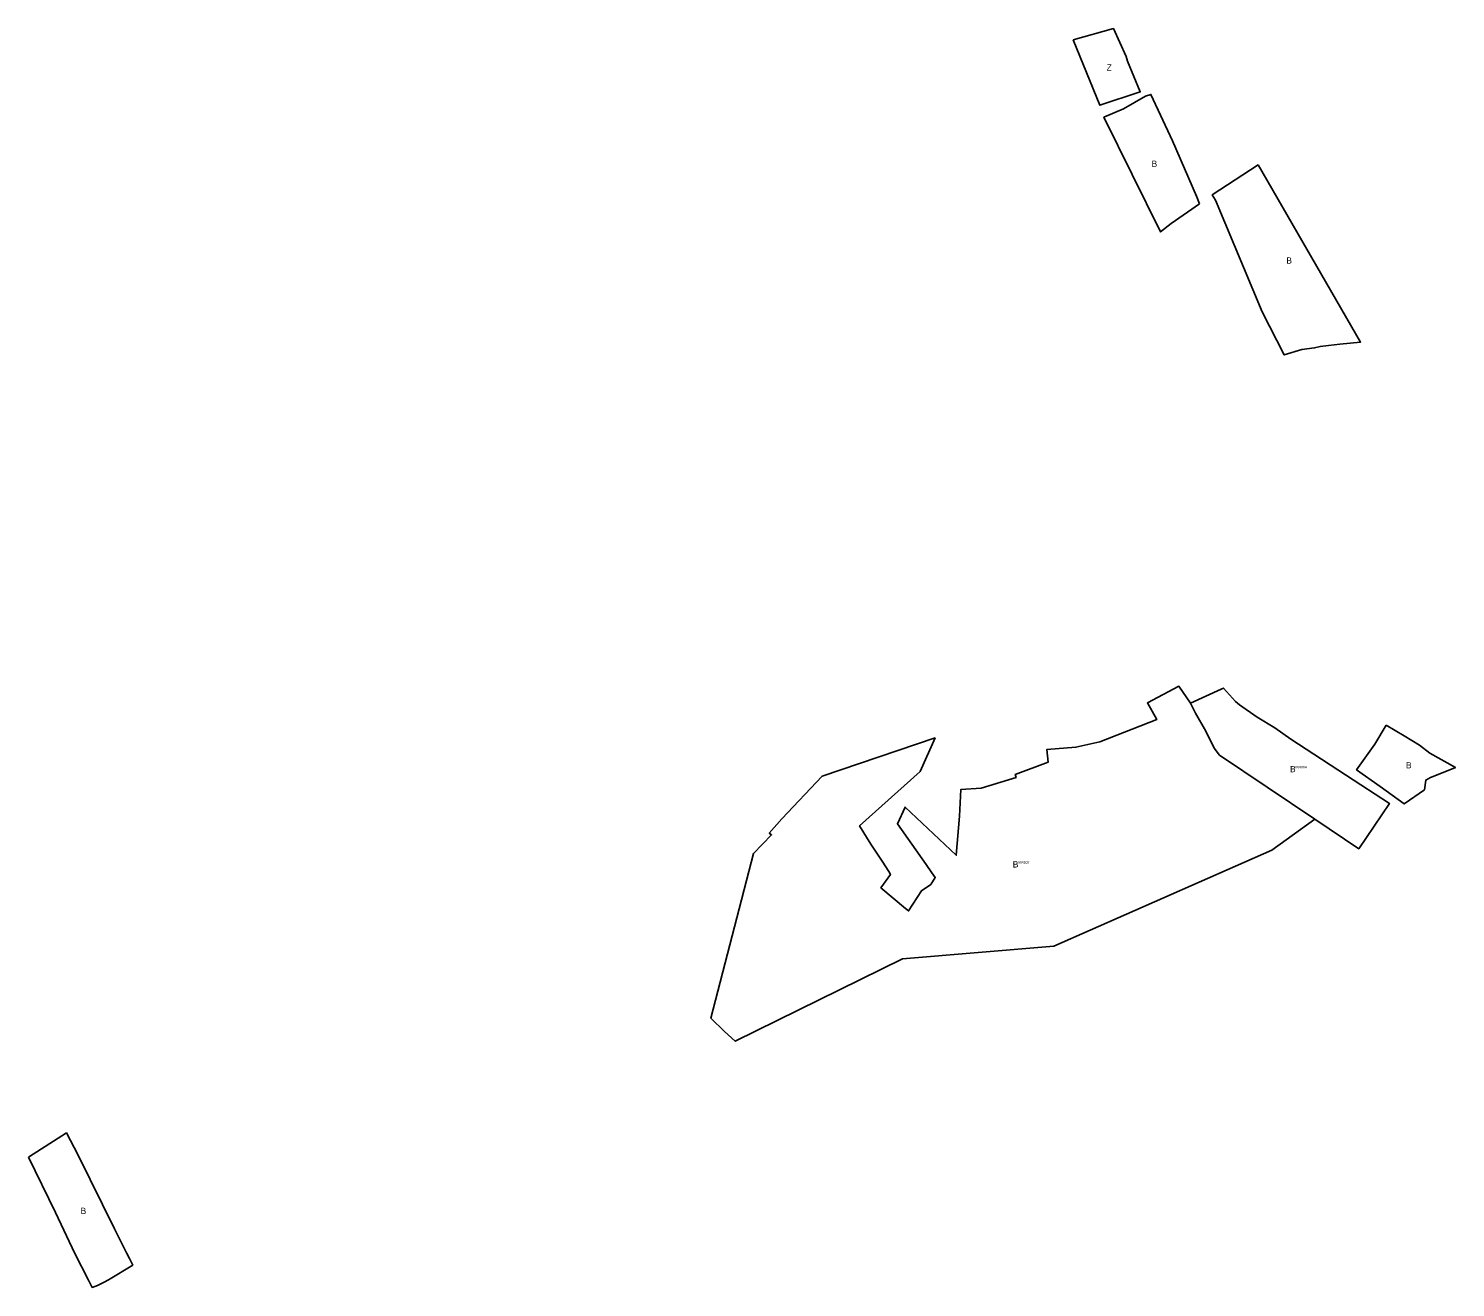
# Model space of a CAD drawing. Extents: x -476493 to -466317, y -1156890 to -1150260.
# Drawn here: x -476129 to -474988, y -1154781 to -1153774 of the extents above; entities that cross this region are included whole.
import ezdxf

# ---------------------------------------------------------------- set-up
doc = ezdxf.new("R2010")
doc.units = 0
doc.layers.add('Vrstva 1', color=7, linetype='Continuous')
doc.layers.add('Vrstva 11', color=7, linetype='Continuous')

msp = doc.modelspace()

# ---------------------------------------------------------------- linework, layer by layer
at = {"layer": 'Vrstva 1'}
for points in [[(-475192.45, -1153914.62), (-475215.07, -1153930.52), (-475223.503, -1153937.123), (-475268.847, -1153845.478), (-475253.15, -1153838.77), (-475235.63, -1153828.6), (-475231.265, -1153827.163), (-475214.09, -1153864.2), (-475194.83, -1153908.45)], [(-475145.44, -1153883.48), (-475063.58, -1154025.3), (-475080.16, -1154026.93), (-475089.35, -1154028.11), (-475095.96, -1154028.81), (-475100.4, -1154029.99), (-475110.67, -1154031.27), (-475124.67, -1154035.5), (-475142.41, -1154000.99), (-475179.63, -1153911.72), (-475182.23, -1153907.61)], [(-475100.158, -1154406.787), (-475134.57, -1154431.71), (-475308.932, -1154508.331), (-475430.09, -1154518.4), (-475563.78, -1154584.46), (-475572.47, -1154576.56), (-475583.335, -1154565.995), (-475549.05, -1154434.42), (-475534.68, -1154419.46), (-475536.48, -1154417.98), (-475526.41, -1154406.53), (-475494.22, -1154372.47), (-475403.93, -1154341.91), (-475415.73, -1154368.66), (-475464.31, -1154412.11), (-475455.17, -1154426.87), (-475446.29, -1154440.3), (-475440.86, -1154448.69), (-475439.67, -1154451.16), (-475447.27, -1154461.63), (-475427.53, -1154478.31), (-475425.16, -1154480.19), (-475414.79, -1154464.09), (-475407.28, -1154459.06), (-475403.73, -1154453.53), (-475406.38, -1154449.77), (-475411.13, -1154443.03), (-475434.04, -1154410.53), (-475427.92, -1154397.1), (-475386.94, -1154435.66), (-475384.38, -1154404.56), (-475383.351, -1154383.147), (-475367, -1154382.04), (-475339.15, -1154373.45), (-475339.75, -1154370.98), (-475313.58, -1154361.31), (-475314.57, -1154351.14), (-475291.27, -1154349.26), (-475272.21, -1154345.11), (-475226.62, -1154327.16), (-475234.08, -1154313.87), (-475208.89, -1154300.51), (-475199.49, -1154314.07), (-475195.7, -1154321.94), (-475187.29, -1154336.45), (-475180.58, -1154350.05), (-475176.33, -1154355.68)], [(-475100.158, -1154406.787), (-475176.33, -1154355.68), (-475180.58, -1154350.05), (-475187.29, -1154336.45), (-475195.7, -1154321.94), (-475199.49, -1154314.07), (-475175.11, -1154302.98), (-475173.08, -1154302.03), (-475163.72, -1154312.61), (-475160.47, -1154315.32), (-475146.22, -1154325.36), (-475132.12, -1154333.91), (-475119.23, -1154342.86), (-475063.35, -1154379.48), (-475040.444, -1154394.18), (-475064.971, -1154430.5)], [(-475043.08, -1154331.7), (-475028.7, -1154340.11), (-475016.56, -1154347.64), (-475008.15, -1154353.95), (-474987.67, -1154365.61), (-474990.86, -1154366.97), (-475007.68, -1154373.54), (-475011.47, -1154375.51), (-475012.35, -1154383.24), (-475028.77, -1154394.67), (-475047.89, -1154380.7), (-475066.74, -1154367.27), (-475052.16, -1154346.76)], [(-476129.01, -1154677.14), (-476098.66, -1154657.81), (-476089.33, -1154675.44), (-476060.26, -1154734.36), (-476050.68, -1154753.77), (-476048.14, -1154758.18), (-476045.59, -1154763.43), (-476064.92, -1154775.13), (-476068.48, -1154777), (-476073.91, -1154779.71), (-476078.02, -1154781.36), (-476081.07, -1154775.6), (-476091.92, -1154754.07), (-476107.35, -1154721.35)]]:
    msp.add_lwpolyline(points, close=True, dxfattribs=at)
at = {"layer": 'Vrstva 11'}
msp.add_lwpolyline([(-475293.51, -1153783.59), (-475261.27, -1153774.5), (-475250.99, -1153796.89), (-475249.91, -1153800.47), (-475239.84, -1153825.14), (-475272.2, -1153835.85)], close=True, dxfattribs=at)

# ---------------------------------------------------------------- texts
at = {"layer": 'Vrstva 1'}
for s, height, p in [('Z', 5, (-475266.675, -1153808.175)), ('B', 5, (-475230.648, -1153885.143)), ('B', 5, (-475122.905, -1153962.49)), ('B', 5, (-475027.205, -1154366.185)), ('1: VKR004', 2, (-475119.967, -1154366.265)), ('B', 5, (-475119.967, -1154369.265)), ('1: VKR007', 2, (-475341.746, -1154442.485)), ('B', 5, (-475341.746, -1154445.485)), ('B', 5, (-476087.3, -1154722.585))]:
    msp.add_text(s, height=height, dxfattribs=at).set_placement(p)

doc.saveas('drawing.dxf')
